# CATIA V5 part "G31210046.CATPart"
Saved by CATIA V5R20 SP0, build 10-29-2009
Part number: G31210046
Revision: 7
Definition: design
Nomenclature: G31210046
Source: made
Description: NOT SPECIFIED
Bounding box of the stored display mesh (mm): x -5 to 46, y -8 to 8, z -8 to 8
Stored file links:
  C:\Users\Raffaele\Desktop\3D X SITO CF\BOLEX\23-BUSH REF 312\G31210046.CATPart

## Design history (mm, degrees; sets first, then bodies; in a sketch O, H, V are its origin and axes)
Body1 "MANIFOLD_SOLID_BREP #10187" (main body)
  Solid1: solid without history
Body2 "MANIFOLD_SOLID_BREP #10330"
  Solid2: solid without history
Body3 "MANIFOLD_SOLID_BREP #10473"
  Solid3: solid without history
Body4 "MANIFOLD_SOLID_BREP #10616"
  Solid4: solid without history
Body5 "MANIFOLD_SOLID_BREP #10759"
  Solid5: solid without history
Body6 "MANIFOLD_SOLID_BREP #10904"
  Solid6: solid without history
Body7 "MANIFOLD_SOLID_BREP #11049"
  Solid7: solid without history
Body8 "MANIFOLD_SOLID_BREP #11194"
  Solid8: solid without history
Body9 "MANIFOLD_SOLID_BREP #11339"
  Solid9: solid without history
Body10 "MANIFOLD_SOLID_BREP #11484"
  Solid10: solid without history
Body11 "MANIFOLD_SOLID_BREP #11629"
  Solid11: solid without history
Body12 "MANIFOLD_SOLID_BREP #11774"
  Solid12: solid without history
Body13 "MANIFOLD_SOLID_BREP #11919"
  Solid13: solid without history
Body14 "MANIFOLD_SOLID_BREP #12064"
  Solid14: solid without history
Body15 "MANIFOLD_SOLID_BREP #12209"
  Solid15: solid without history
Body16 "MANIFOLD_SOLID_BREP #12354"
  Solid16: solid without history
Body17 "MANIFOLD_SOLID_BREP #12499"
  Solid17: solid without history
Body18 "MANIFOLD_SOLID_BREP #12644"
  Solid18: solid without history
Body19 "MANIFOLD_SOLID_BREP #12789"
  Solid19: solid without history
Body20 "MANIFOLD_SOLID_BREP #12934"
  Solid20: solid without history
Body21 "MANIFOLD_SOLID_BREP #13079"
  Solid21: solid without history
Body22 "MANIFOLD_SOLID_BREP #13224"
  Solid22: solid without history
Body23 "MANIFOLD_SOLID_BREP #13369"
  Solid23: solid without history
Body24 "MANIFOLD_SOLID_BREP #13514"
  Solid24: solid without history
Body25 "MANIFOLD_SOLID_BREP #13659"
  Solid25: solid without history
Body26 "MANIFOLD_SOLID_BREP #13804"
  Solid26: solid without history
Body27 "MANIFOLD_SOLID_BREP #13949"
  Solid27: solid without history
Body28 "MANIFOLD_SOLID_BREP #14094"
  Solid28: solid without history
Body29 "MANIFOLD_SOLID_BREP #14239"
  Solid29: solid without history
Body30 "MANIFOLD_SOLID_BREP #14384"
  Solid30: solid without history
Body31 "MANIFOLD_SOLID_BREP #14529"
  Solid31: solid without history
Body32 "MANIFOLD_SOLID_BREP #14674"
  Solid32: solid without history
Body33 "MANIFOLD_SOLID_BREP #14819"
  Solid33: solid without history
Body34 "MANIFOLD_SOLID_BREP #14964"
  Solid34: solid without history
Body35 "MANIFOLD_SOLID_BREP #15107"
  Solid35: solid without history
Body36 "MANIFOLD_SOLID_BREP #15250"
  Solid36: solid without history
Body37 "MANIFOLD_SOLID_BREP #15395"
  Solid37: solid without history
Body38 "MANIFOLD_SOLID_BREP #15540"
  Solid38: solid without history
Body39 "MANIFOLD_SOLID_BREP #15685"
  Solid39: solid without history
Body40 "MANIFOLD_SOLID_BREP #15830"
  Solid40: solid without history
Body41 "MANIFOLD_SOLID_BREP #15975"
  Solid41: solid without history
Body42 "MANIFOLD_SOLID_BREP #16120"
  Solid42: solid without history
Body43 "MANIFOLD_SOLID_BREP #16265"
  Solid43: solid without history
Body44 "MANIFOLD_SOLID_BREP #16410"
  Solid44: solid without history
Body45 "MANIFOLD_SOLID_BREP #16555"
  Solid45: solid without history
Body46 "MANIFOLD_SOLID_BREP #16700"
  Solid46: solid without history
Body47 "MANIFOLD_SOLID_BREP #16845"
  Solid47: solid without history
Body48 "MANIFOLD_SOLID_BREP #16990"
  Solid48: solid without history
Body49 "MANIFOLD_SOLID_BREP #17135"
  Solid49: solid without history
Body50 "MANIFOLD_SOLID_BREP #17280"
  Solid50: solid without history
Body51 "MANIFOLD_SOLID_BREP #17425"
  Solid51: solid without history
Body52 "MANIFOLD_SOLID_BREP #17570"
  Solid52: solid without history
Body53 "MANIFOLD_SOLID_BREP #17715"
  Solid53: solid without history
Body54 "MANIFOLD_SOLID_BREP #17860"
  Solid54: solid without history
Body55 "MANIFOLD_SOLID_BREP #18005"
  Solid55: solid without history
Body56 "MANIFOLD_SOLID_BREP #18150"
  Solid56: solid without history
Body57 "MANIFOLD_SOLID_BREP #18293"
  Solid57: solid without history
Body58 "MANIFOLD_SOLID_BREP #18436"
  Solid58: solid without history
Body59 "MANIFOLD_SOLID_BREP #18581"
  Solid59: solid without history
Body60 "MANIFOLD_SOLID_BREP #18726"
  Solid60: solid without history
Body61 "MANIFOLD_SOLID_BREP #18871"
  Solid61: solid without history
Body62 "MANIFOLD_SOLID_BREP #19016"
  Solid62: solid without history
Body63 "MANIFOLD_SOLID_BREP #19161"
  Solid63: solid without history
Body64 "MANIFOLD_SOLID_BREP #19306"
  Solid64: solid without history
Body65 "MANIFOLD_SOLID_BREP #19449"
  Solid65: solid without history
Body66 "MANIFOLD_SOLID_BREP #19592"
  Solid66: solid without history
Body67 "MANIFOLD_SOLID_BREP #19737"
  Solid67: solid without history
Body68 "MANIFOLD_SOLID_BREP #19882"
  Solid68: solid without history
Body69 "MANIFOLD_SOLID_BREP #20027"
  Solid69: solid without history
Body70 "MANIFOLD_SOLID_BREP #20172"
  Solid70: solid without history
Body71 "MANIFOLD_SOLID_BREP #20317"
  Solid71: solid without history
Body72 "MANIFOLD_SOLID_BREP #20462"
  Solid72: solid without history
Body73 "MANIFOLD_SOLID_BREP #20607"
  Solid73: solid without history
